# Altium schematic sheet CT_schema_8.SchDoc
size 251 x 159 mm
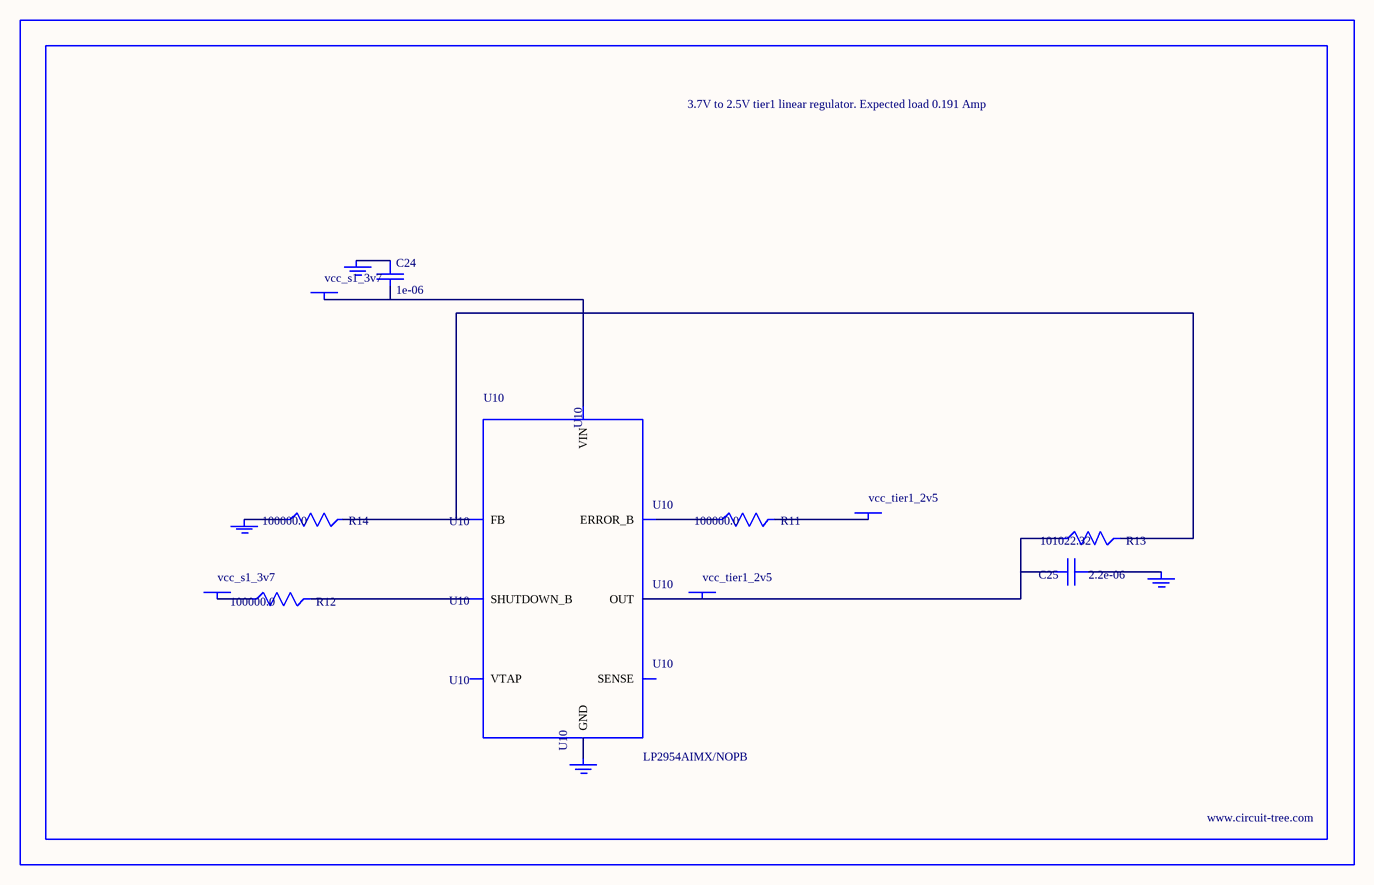
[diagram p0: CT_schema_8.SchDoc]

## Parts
BORDER7  (no value)
C24  1e-06  [EXV-9B]
C25  2.2e-06  [EXV-9B]
GND_INSTANCE_7_0  (no value)
GND_INSTANCE_7_1  (no value)
GND_INSTANCE_7_2  (no value)
GND_INSTANCE_7_3  (no value)
POWER_INSTANCE_7_0  vcc_s1_3v7
POWER_INSTANCE_7_1  vcc_tier1_2v5
POWER_INSTANCE_7_2  vcc_s1_3v7
POWER_INSTANCE_7_3  vcc_tier1_2v5
R11  100000.0  [R0603]
R12  100000.0  [R0603]
R13  101022.32  [R0603]
R14  100000.0  [R0603]
U10  LP2954AIMX/NOPB  [LP2954]

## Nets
NetC24_1: C24.1 GND_INSTANCE_7_2.0(GND)
NetC24_2: C24.2 POWER_INSTANCE_7_2.0(PWR) U10.8(VIN)
NetC25_1: C25.1 GND_INSTANCE_7_0.0(GND)
NetC25_2: C25.2 POWER_INSTANCE_7_3.0(PWR) R13.1 U10.1(OUT)
NetGND_INSTANCE_7_1_0: GND_INSTANCE_7_1.0(GND) R14.1
NetGND_INSTANCE_7_3_0: GND_INSTANCE_7_3.0(GND) U10.4(GND)
NetPOWER_INSTANCE_7_0_0: POWER_INSTANCE_7_0.0(PWR) R12.1
NetPOWER_INSTANCE_7_1_0: POWER_INSTANCE_7_1.0(PWR) R11.2
NetR11_1: R11.1 U10.5(ERROR_B)
NetR12_2: R12.2 U10.3(SHUTDOWN_B)
NetR13_2: R13.2 R14.2 U10.7(FB)

Not connected (* = marked no-connect by the designer): U10 2(SENSE) 6(VTAP)

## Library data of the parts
BORDER7 = BORDER_PAGE7
C24 = EDK105M050A9BAA
C25 = EDK225M050A9BAA
GND_INSTANCE_7_0-GND_INSTANCE_7_3 = GND
POWER_INSTANCE_7_0-POWER_INSTANCE_7_3 = PWR
R11 R12 R14 = RC0603JR-07100KL
R13 = R13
